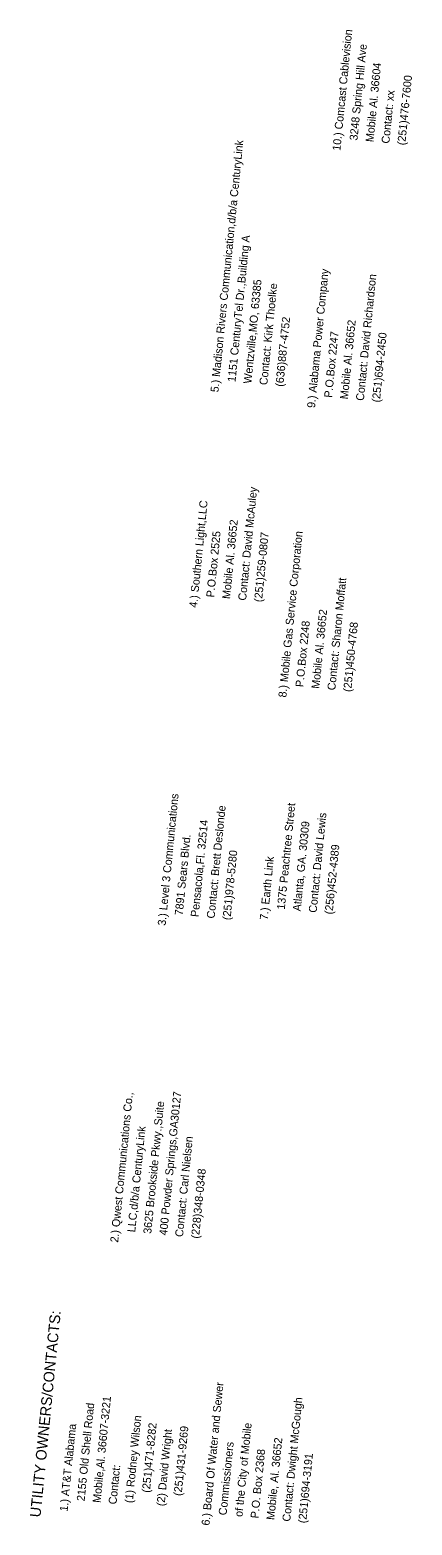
# Model space of a CAD drawing. Extents: x 1796454 to 1799611, y 245396 to 251965.
# Drawn here: x 1797696 to 1798054, y 245396 to 246797 of the extents above; entities that cross this region are included whole.
import ezdxf

# ---------------------------------------------------------------- set-up
doc = ezdxf.new("R2010")
doc.units = 0
doc.layers.add('2', color=7, linetype='Continuous')

msp = doc.modelspace()

# ---------------------------------------------------------------- texts
at = {"layer": '2'}
for s, height, rotation, p in [('10.) Comcast Cablevision', 7.5, 84.3427, (1797986.9, 246683.7)), ('    3248 Spring Hill Ave', 7.5, 84.3427, (1798001.8, 246682.2)), ('    Mobile Al. 36604', 7.5, 84.3427, (1798016.8, 246680.7)), ('    (251)476-7600', 7.5, 84.3427, (1798046.6, 246677.8)), ('    Contact: xx', 7.5, 84.3427, (1798031.7, 246679.3)), ('5.) Madison Rivers Communication,d/b/a CenturyLink', 7.5, 84.3427, (1797872.6, 246457.3)), ('    1151 CenturyTel Dr.,Building A', 7.5, 84.3427, (1797887.5, 246455.8)), ('9.) Alabama Power Company', 7.5, 84.3427, (1797963.1, 246442.6)), ('    Contact: David Richardson', 7.5, 84.3427, (1798007.8, 246438.2)), ('    Wentzville,MO, 63385', 7.5, 84.3427, (1797902.4, 246454.3)), ('    Contact: Kirk Thoelke', 7.5, 84.3427, (1797917.3, 246452.9)), ('    (636)887-4752', 7.5, 84.3427, (1797932.3, 246451.4)), ('    Mobile Al. 36652', 7.5, 84.3427, (1797992.9, 246439.6)), ('    P.O.Box 2247', 7.5, 84.3427, (1797978, 246441.1)), ('    (251)694-2450', 7.5, 84.3427, (1798022.8, 246436.7)), ('    Contact: David McAuley', 7.5, 84.3427, (1797897.4, 246250.9)), ('4.) Southern Light,LLC', 7.5, 84.3427, (1797852.6, 246255.4)), ('    P.O.Box 2525', 7.5, 84.3427, (1797867.5, 246253.9)), ('    Mobile Al. 36652', 7.5, 84.3427, (1797882.4, 246252.4)), ('    (251)259-0807', 7.5, 84.3427, (1797912.3, 246249.5)), ('8.) Mobile Gas Service Corporation', 7.5, 84.3427, (1797936.2, 246171.2)), ('    Contact: Sharon Moffatt', 7.5, 84.3427, (1797981, 246166.8)), ('    P.O.Box 2248', 7.5, 84.3427, (1797951.1, 246169.8)), ('    Mobile Al. 36652', 7.5, 84.3427, (1797966.1, 246168.3)), ('    (251)450-4768', 7.5, 84.3427, (1797995.9, 246165.3)), ('3.) Level 3 Communications', 7.5, 84.3427, (1797823.1, 245957.3)), ('    Contact: Brett Deslonde', 7.5, 84.3427, (1797867.9, 245952.9)), ('    1375 Peachtree Street', 7.5, 84.3427, (1797933.7, 245961.2)), ('    Contact: David Lewis', 7.5, 84.3427, (1797963.5, 245958.3)), ('    Pensacola,Fl. 32514', 7.5, 84.3427, (1797852.9, 245954.3)), ('    Atlanta, GA. 30309', 7.5, 84.3427, (1797948.6, 245959.7)), ('    7891 Sears Blvd.', 7.5, 84.3427, (1797838, 245955.8)), ('    (256)452-4389', 7.5, 84.3427, (1797978.5, 245956.8)), ('    (251)978-5280', 7.5, 84.3427, (1797882.8, 245951.4)), ('7.) Earth Link', 7.5, 84.3427, (1797918.8, 245962.7)), ('2.) Qwest Communications Co.,', 7.5, 84.3427, (1797778.6, 245660.3)), ('    400 Powder Springs,GA30127', 7.5, 84.3427, (1797823.4, 245655.9)), ('    3625 Brookside Pkwy.,Suite ', 7.5, 84.3427, (1797808.5, 245657.3)), ('    LLC,d/b/a CenturyLink', 7.5, 84.3427, (1797793.5, 245658.8)), ('    Contact: Carl Nielsen', 7.5, 84.3427, (1797838.3, 245654.4)), ('    (228)348-0348', 7.5, 84.3427, (1797853.3, 245652.9)), ('UTILITY OWNERS/CONTACTS:', 10, 84.3469, (1797705.8, 245402.6)), ('6.) Board Of Water and Sewer ', 7.5, 84.3427, (1797864.2, 245395)), ('    Mobile,Al. 36607-3221', 7.5, 84.3427, (1797761, 245405.2)), ('    Contact: Dwight McGough', 7.5, 84.3427, (1797938.8, 245387.6)), ('    2155 Old Shell Road', 7.5, 84.3427, (1797746.1, 245406.7)), ('1.) AT&T Alabama', 7.5, 84.3427, (1797731.2, 245408.2)), ('     (1) Rodney Wilson', 7.5, 84.3427, (1797790.9, 245402.2)), ('         (251)471-8282', 7.5, 84.3427, (1797805.8, 245400.8)), ('     (2) David Wright', 7.5, 84.3427, (1797820.7, 245399.3)), ('         (251)431-9269', 7.5, 84.3427, (1797835.6, 245397.8)), ('    of the City of Mobile', 7.5, 84.3427, (1797894, 245392)), ('    Commissioners', 7.5, 84.3427, (1797879.1, 245393.5)), ('    Mobile, Al. 36652', 7.5, 84.3427, (1797923.9, 245389.1)), ('    P.O. Box 2368', 7.5, 84.3427, (1797909, 245390.6)), ('    (251)694-3191', 7.5, 84.3427, (1797953.7, 245386.1)), ('    Contact:', 7.5, 84.3427, (1797775.9, 245403.7))]:
    msp.add_text(s, height=height, rotation=rotation, dxfattribs=at).set_placement(p)

doc.saveas('drawing.dxf')
